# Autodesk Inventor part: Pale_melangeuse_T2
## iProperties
Shininess: 64.0
Length Units: 11269
Angle Units: 11279
Time Units: 11290
Mass Units: 11283
Length Display Precision: 3
Angle Display Precision: 2
Compacted: True
Part Number: Pale_melangeuse_T2
Document SubType Name: Modeling
Created: 2008-02
Material: Acier inoxydable, austénitique
Designer: Pascal
Density: 0.0
Volumn: 0.0
Area: 0.0
PropertySet Name: Model Information
Control State: 0
Master: False
Checked Out: False
DESIGNATION: pièce
Author: Pascal
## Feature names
1. Extrusion1
